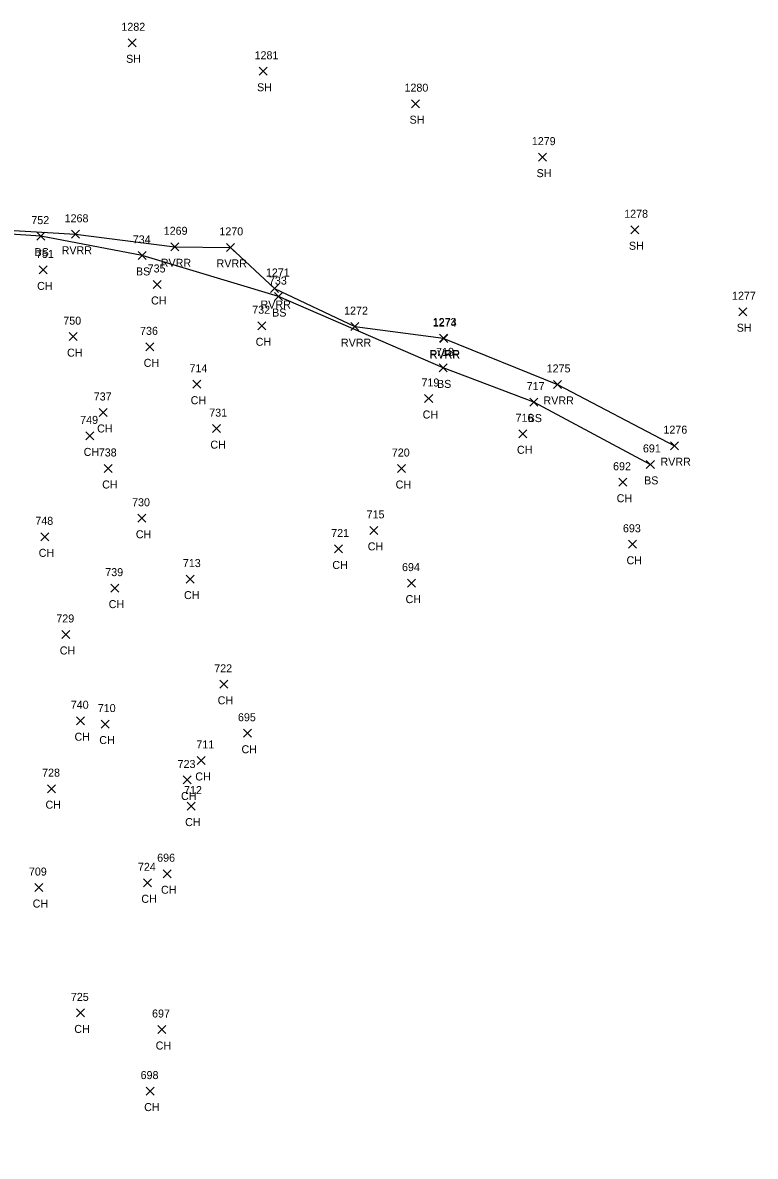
# Model space of a CAD drawing. Extents: x 1885914 to 1887218, y 756253 to 760620.
# Drawn here: x 1887034.9 to 1887217.9, y 759954.5 to 760237.8 of the extents above; entities that cross this region are included whole.
import ezdxf

# ---------------------------------------------------------------- set-up
doc = ezdxf.new("R2010")
doc.units = 0
for name, color, linetype in [('L_A', 7, 'Continuous'), ('L_I', 7, 'Continuous'), ('L_TIC', 7, 'Continuous'), ('LAWE', 7, 'Continuous'), ('LELB', 7, 'Continuous')]:
    doc.layers.add(name, color=color, linetype=linetype)

msp = doc.modelspace()

# ---------------------------------------------------------------- linework, layer by layer
at = {"layer": 'L_TIC'}
for points in [[(1887061.26, 760231.77), (1887063.26, 760233.77)], [(1887063.26, 760231.77), (1887061.26, 760233.77)], [(1887093.96, 760224.65), (1887095.96, 760226.65)], [(1887095.96, 760224.65), (1887093.96, 760226.65)], [(1887132.05, 760216.55), (1887134.05, 760218.55)], [(1887134.05, 760216.55), (1887132.05, 760218.55)], [(1887163.77, 760203.19), (1887165.77, 760205.19)], [(1887165.77, 760203.19), (1887163.77, 760205.19)], [(1887186.84, 760185.04), (1887188.84, 760187.04)], [(1887188.84, 760185.04), (1887186.84, 760187.04)], [(1887038.44, 760183.45), (1887040.44, 760185.45)], [(1887040.44, 760183.45), (1887038.44, 760185.45)], [(1887047.13, 760183.91), (1887049.13, 760185.91)], [(1887049.13, 760183.91), (1887047.13, 760185.91)], [(1887071.89, 760180.79), (1887073.89, 760182.79)], [(1887073.89, 760180.79), (1887071.89, 760182.79)], [(1887085.82, 760180.64), (1887087.82, 760182.64)], [(1887087.82, 760180.64), (1887085.82, 760182.64)], [(1887063.77, 760178.63), (1887065.77, 760180.63)], [(1887065.77, 760178.63), (1887063.77, 760180.63)], [(1887039.03, 760175), (1887041.03, 760177)], [(1887041.03, 760175), (1887039.03, 760177)], [(1887067.5, 760171.37), (1887069.5, 760173.37)], [(1887069.5, 760171.37), (1887067.5, 760173.37)], [(1887096.78, 760170.36), (1887098.78, 760172.36)], [(1887098.78, 760170.36), (1887096.78, 760172.36)], [(1887097.78, 760168.34), (1887099.78, 760170.34)], [(1887099.78, 760168.34), (1887097.78, 760170.34)], [(1887213.77, 760164.56), (1887215.77, 760166.56)], [(1887215.77, 760164.56), (1887213.77, 760166.56)], [(1887093.61, 760161.05), (1887095.61, 760163.05)], [(1887095.61, 760161.05), (1887093.61, 760163.05)], [(1887116.89, 760160.83), (1887118.89, 760162.83)], [(1887118.89, 760160.83), (1887116.89, 760162.83)], [(1887046.51, 760158.33), (1887048.51, 760160.33)], [(1887048.51, 760158.33), (1887046.51, 760160.33)], [(1887139.02, 760157.99), (1887141.02, 760159.99)], [(1887141.02, 760157.99), (1887139.02, 760159.99)], [(1887139.06, 760157.85), (1887141.06, 760159.85)], [(1887141.06, 760157.85), (1887139.06, 760159.85)], [(1887065.65, 760155.78), (1887067.65, 760157.78)], [(1887067.65, 760155.78), (1887065.65, 760157.78)], [(1887138.96, 760150.52), (1887140.96, 760152.52)], [(1887140.96, 760150.52), (1887138.96, 760152.52)], [(1887077.38, 760146.44), (1887079.38, 760148.44)], [(1887079.38, 760146.44), (1887077.38, 760148.44)], [(1887167.47, 760146.39), (1887169.47, 760148.39)], [(1887169.47, 760146.39), (1887167.47, 760148.39)], [(1887135.31, 760142.87), (1887137.31, 760144.87)], [(1887137.31, 760142.87), (1887135.31, 760144.87)], [(1887161.59, 760141.97), (1887163.59, 760143.97)], [(1887163.59, 760141.97), (1887161.59, 760143.97)], [(1887054.02, 760139.38), (1887056.02, 760141.38)], [(1887056.02, 760139.38), (1887054.02, 760141.38)], [(1887082.31, 760135.34), (1887084.31, 760137.34)], [(1887084.31, 760135.34), (1887082.31, 760137.34)], [(1887158.86, 760134.05), (1887160.86, 760136.05)], [(1887160.86, 760134.05), (1887158.86, 760136.05)], [(1887050.65, 760133.52), (1887052.65, 760135.52)], [(1887052.65, 760133.52), (1887050.65, 760135.52)], [(1887196.69, 760131.08), (1887198.69, 760133.08)], [(1887198.69, 760131.08), (1887196.69, 760133.08)], [(1887190.67, 760126.4), (1887192.67, 760128.4)], [(1887192.67, 760126.4), (1887190.67, 760128.4)], [(1887055.28, 760125.38), (1887057.28, 760127.38)], [(1887057.28, 760125.38), (1887055.28, 760127.38)], [(1887128.56, 760125.37), (1887130.56, 760127.37)], [(1887130.56, 760125.37), (1887128.56, 760127.37)], [(1887183.77, 760121.94), (1887185.77, 760123.94)], [(1887185.77, 760121.94), (1887183.77, 760123.94)], [(1887063.69, 760112.94), (1887065.69, 760114.94)], [(1887065.69, 760112.94), (1887063.69, 760114.94)], [(1887121.6, 760109.91), (1887123.6, 760111.91)], [(1887123.6, 760109.91), (1887121.6, 760111.91)], [(1887039.43, 760108.3), (1887041.43, 760110.3)], [(1887041.43, 760108.3), (1887039.43, 760110.3)], [(1887186.24, 760106.44), (1887188.24, 760108.44)], [(1887188.24, 760106.44), (1887186.24, 760108.44)], [(1887112.76, 760105.26), (1887114.76, 760107.26)], [(1887114.76, 760105.26), (1887112.76, 760107.26)], [(1887075.72, 760097.74), (1887077.72, 760099.74)], [(1887077.72, 760097.74), (1887075.72, 760099.74)], [(1887056.91, 760095.48), (1887058.91, 760097.48)], [(1887058.91, 760095.48), (1887056.91, 760097.48)], [(1887131.06, 760096.73), (1887133.06, 760098.73)], [(1887133.06, 760096.73), (1887131.06, 760098.73)], [(1887044.69, 760083.9), (1887046.69, 760085.9)], [(1887046.69, 760083.9), (1887044.69, 760085.9)], [(1887084.12, 760071.44), (1887086.12, 760073.44)], [(1887086.12, 760071.44), (1887084.12, 760073.44)], [(1887048.38, 760062.34), (1887050.38, 760064.34)], [(1887050.38, 760062.34), (1887048.38, 760064.34)], [(1887054.55, 760061.51), (1887056.55, 760063.51)], [(1887056.55, 760061.51), (1887054.55, 760063.51)], [(1887090.09, 760059.21), (1887092.09, 760061.21)], [(1887092.09, 760059.21), (1887090.09, 760061.21)], [(1887078.53, 760052.41), (1887080.53, 760054.41)], [(1887080.53, 760052.41), (1887078.53, 760054.41)], [(1887074.97, 760047.53), (1887076.97, 760049.53)], [(1887076.97, 760047.53), (1887074.97, 760049.53)], [(1887041.13, 760045.36), (1887043.13, 760047.36)], [(1887043.13, 760045.36), (1887041.13, 760047.36)], [(1887076, 760041.01), (1887078, 760043.01)], [(1887078, 760041.01), (1887076, 760043.01)], [(1887069.97, 760024.1), (1887071.97, 760026.1)], [(1887071.97, 760024.1), (1887069.97, 760026.1)], [(1887065.06, 760021.83), (1887067.06, 760023.83)], [(1887067.06, 760021.83), (1887065.06, 760023.83)], [(1887037.92, 760020.65), (1887039.92, 760022.65)], [(1887039.92, 760020.65), (1887037.92, 760022.65)], [(1887048.32, 759989.32), (1887050.32, 759991.32)], [(1887050.32, 759989.32), (1887048.32, 759991.32)], [(1887068.64, 759985.17), (1887070.64, 759987.17)], [(1887070.64, 759985.17), (1887068.64, 759987.17)], [(1887065.77, 759969.78), (1887067.77, 759971.78)], [(1887067.77, 759969.78), (1887065.77, 759971.78)]]:
    msp.add_lwpolyline(points, dxfattribs=at)
at = {"layer": 'LAWE'}
msp.add_lwpolyline([(1886829.4, 760164.97), (1886849.11, 760176.99), (1886861.69, 760175.78), (1886878.16, 760179.2), (1886901.82, 760185.36), (1886912.29, 760190.98), (1886926.33, 760202.55), (1886943.61, 760204.04), (1886953.51, 760196.79), (1886972.65, 760200.09), (1886988.87, 760206.19), (1886998.76, 760200.58), (1887010.54, 760190.52), (1887024.26, 760186.39), (1887048.13, 760184.91), (1887072.89, 760181.79), (1887086.82, 760181.64), (1887097.78, 760171.36), (1887117.89, 760161.83), (1887140.02, 760158.99), (1887140.06, 760158.85), (1887168.47, 760147.39), (1887197.69, 760132.08)], dxfattribs=at)
at = {"layer": 'LELB'}
msp.add_lwpolyline([(1887191.67, 760127.4), (1887162.59, 760142.97), (1887139.96, 760151.52), (1887098.78, 760169.34), (1887064.77, 760179.63), (1887039.44, 760184.45), (1887015.43, 760186.04), (1886988.17, 760195.78), (1886958.13, 760192.47), (1886941.93, 760196.3), (1886915.34, 760186.03), (1886875.72, 760169.95), (1886843.17, 760163.26), (1886814.02, 760157.37), (1886794.47, 760144.1), (1886725.54, 760103.53), (1886704.64, 760082.53), (1886687.39, 760060.16), (1886675.38, 760043.91), (1886662.89, 760014.32), (1886651.59, 759963.58), (1886647.85, 759929.2)], dxfattribs=at)

# ---------------------------------------------------------------- texts
at = {"layer": 'L_A'}
for s, p in [('SH', (1887060.75, 760227.77)), ('SH', (1887093.45, 760220.65)), ('SH', (1887131.54, 760212.55)), ('SH', (1887163.26, 760199.19)), ('BS', (1887037.88, 760179.45)), ('RVRR', (1887044.65, 760179.91)), ('SH', (1887186.32, 760181.04)), ('RVRR', (1887069.4, 760176.79)), ('RVRR', (1887083.34, 760176.64)), ('BS', (1887063.21, 760174.63)), ('CH', (1887038.52, 760171)), ('CH', (1887066.98, 760167.37)), ('RVRR', (1887094.3, 760166.36)), ('BS', (1887097.22, 760164.34)), ('SH', (1887213.25, 760160.56)), ('CH', (1887093.1, 760157.05)), ('RVRR', (1887114.4, 760156.83)), ('CH', (1887046, 760154.33)), ('RVRR', (1887136.53, 760153.99)), ('RVRR', (1887136.57, 760153.85)), ('CH', (1887065.13, 760151.78)), ('BS', (1887138.4, 760146.52)), ('CH', (1887076.87, 760142.44)), ('RVRR', (1887164.98, 760142.39)), ('CH', (1887134.8, 760138.87)), ('BS', (1887161.03, 760137.97)), ('CH', (1887053.51, 760135.38)), ('CH', (1887081.79, 760131.34)), ('CH', (1887050.14, 760129.52)), ('CH', (1887158.35, 760130.05)), ('RVRR', (1887194.2, 760127.08)), ('CH', (1887054.77, 760121.38)), ('CH', (1887128.05, 760121.37)), ('BS', (1887190.11, 760122.4)), ('CH', (1887183.26, 760117.94)), ('CH', (1887063.18, 760108.94)), ('CH', (1887121.09, 760105.91)), ('CH', (1887038.92, 760104.3)), ('CH', (1887112.25, 760101.26)), ('CH', (1887185.73, 760102.44)), ('CH', (1887075.21, 760093.74)), ('CH', (1887130.54, 760092.73)), ('CH', (1887056.4, 760091.48)), ('CH', (1887044.18, 760079.9)), ('CH', (1887083.61, 760067.44)), ('CH', (1887047.87, 760058.34)), ('CH', (1887054.04, 760057.51)), ('CH', (1887089.57, 760055.21)), ('CH', (1887078.02, 760048.41)), ('CH', (1887074.46, 760043.53)), ('CH', (1887040.62, 760041.36)), ('CH', (1887075.49, 760037.01)), ('CH', (1887064.55, 760017.83)), ('CH', (1887069.46, 760020.1)), ('CH', (1887037.41, 760016.65)), ('CH', (1887047.8, 759985.32)), ('CH', (1887068.13, 759981.17)), ('CH', (1887065.26, 759965.78))]:
    msp.add_text(s, height=2, dxfattribs=at).set_placement(p)
at = {"layer": 'L_I'}
for s, p in [('1282', (1887059.57, 760235.77)), ('1281', (1887092.83, 760228.65)), ('1280', (1887130.27, 760220.55)), ('1279', (1887162.07, 760207.19)), ('1268', (1887045.39, 760187.91)), ('1278', (1887185.14, 760189.04)), ('752', (1887037.08, 760187.45)), ('734', (1887062.41, 760182.63)), ('1269', (1887070.14, 760184.79)), ('1270', (1887084.04, 760184.64)), ('751', (1887038.24, 760179)), ('735', (1887066.13, 760175.37)), ('1271', (1887095.66, 760174.36)), ('733', (1887096.42, 760172.34)), ('1277', (1887212.07, 760168.56)), ('750', (1887045.06, 760162.33)), ('732', (1887092.25, 760165.05)), ('1272', (1887115.19, 760164.83)), ('736', (1887064.23, 760159.78)), ('1273', (1887137.32, 760161.99)), ('1274', (1887137.37, 760161.85)), ('718', (1887138.16, 760154.52)), ('714', (1887076.58, 760150.44)), ('1275', (1887165.78, 760150.39)), ('719', (1887134.51, 760146.87)), ('717', (1887160.79, 760145.97)), ('737', (1887052.66, 760143.38)), ('749', (1887049.28, 760137.52)), ('731', (1887081.51, 760139.34)), ('716', (1887158.01, 760138.05)), ('1276', (1887194.94, 760135.08)), ('738', (1887053.92, 760129.38)), ('720', (1887127.11, 760129.37)), ('691', (1887189.82, 760130.4)), ('692', (1887182.36, 760125.94)), ('730', (1887062.24, 760116.94)), ('748', (1887038.07, 760112.3)), ('715', (1887120.81, 760113.91)), ('721', (1887111.97, 760109.26)), ('693', (1887184.83, 760110.44)), ('713', (1887074.92, 760101.74)), ('694', (1887129.65, 760100.73)), ('739', (1887055.54, 760099.48)), ('729', (1887043.32, 760087.9)), ('722', (1887082.76, 760075.44)), ('740', (1887046.93, 760066.34)), ('710', (1887053.67, 760065.51)), ('695', (1887088.68, 760063.21)), ('711', (1887078.3, 760056.41)), ('728', (1887039.77, 760049.36)), ('723', (1887073.61, 760051.53)), ('712', (1887075.21, 760045.01)), ('696', (1887068.5, 760028.1)), ('709', (1887036.47, 760024.65)), ('724', (1887063.7, 760025.83)), ('725', (1887046.95, 759993.32)), ('697', (1887067.23, 759989.17)), ('698', (1887064.37, 759973.78))]:
    msp.add_text(s, height=2, dxfattribs=at).set_placement(p)

doc.saveas('drawing.dxf')
